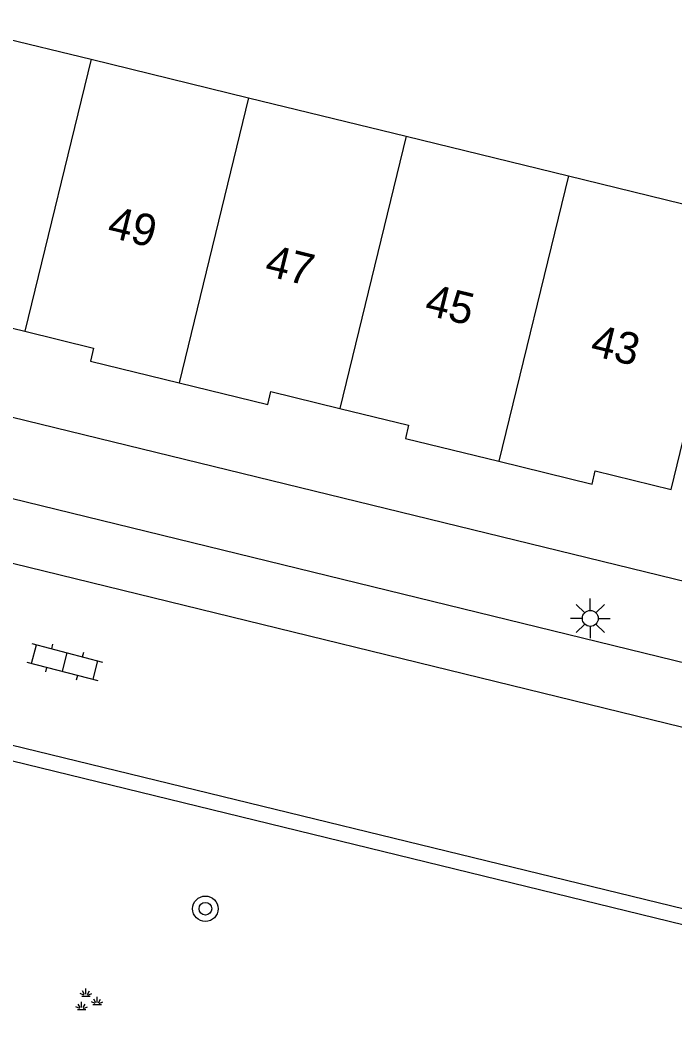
# Model space of a CAD drawing. Extents: x 125000 to 129004, y 397500 to 399008.
# Drawn here: x 126685.74 to 126706.31, y 398431.59 to 398463.62 of the extents above; entities that cross this region are included whole.
import ezdxf

# ---------------------------------------------------------------- set-up
doc = ezdxf.new("R2010")
doc.units = 0
for name, color, linetype in [('gg-anno-huisnummerreeks BGT', 7, 'Continuous'), ('gg-bbg-hoofdgebouw', 7, 'Continuous'), ('gg-bbg-tussenscheiding', 7, 'Continuous'), ('gg-knt-verharding', 7, 'Continuous'), ('gg-knt-verharding nz', 7, 'Continuous'), ('gt-symb-boom', 7, 'Continuous'), ('gt-symb-groenvak', 7, 'Continuous'), ('gt-symb-klinker verharding', 7, 'Continuous'), ('gt-symb-lichtmast', 7, 'Continuous')]:
    doc.layers.add(name, color=color, linetype=linetype)

# ---------------------------------------------------------------- blocks, each defined once
blk = doc.blocks.new('gt0-LMAST')
at = {"layer": 'gt-symb-lichtmast'}
for p, q in [((-0.182, 0.173), (-0.447, 0.438)), ((-0.005, 0.246), (-0.005, 0.621)), ((0.172, 0.173), (0.437, 0.438)), ((-0.255, -0.004), (-0.63, -0.004)), ((-0.182, -0.181), (-0.447, -0.446)), ((-0.005, -0.254), (-0.005, -0.629)), ((0.437, -0.446), (0.172, -0.181)), ((0.245, -0.004), (0.62, -0.004))]:
    blk.add_line(p, q, dxfattribs=at)
blk.add_circle((-0.005, -0.004), 0.25, dxfattribs=at)
blk = doc.blocks.new('gt0-GRVAK')
at = {"layer": 'gt-symb-groenvak'}
for p, q in [((-0.091, 0.211), (-0.156, 0.322)), ((-0.047, 0.214), (-0.047, 0.393)), ((-0.004, 0.211), (0.061, 0.322)), ((-0.11, 0.189), (-0.228, 0.24)), ((-0.182, 0.153), (0.088, 0.153)), ((0.015, 0.189), (0.133, 0.24)), ((0.262, -0.052), (0.197, 0.059)), ((0.305, -0.049), (0.305, 0.13)), ((0.349, -0.052), (0.414, 0.059)), ((-0.245, -0.228), (-0.363, -0.177)), ((-0.318, -0.264), (-0.047, -0.264)), ((-0.226, -0.206), (-0.291, -0.095)), ((-0.183, -0.203), (-0.183, -0.024)), ((-0.139, -0.206), (-0.074, -0.095)), ((-0.12, -0.228), (-0.002, -0.177)), ((0.243, -0.074), (0.125, -0.023)), ((0.17, -0.11), (0.441, -0.11)), ((0.368, -0.074), (0.486, -0.023))]:
    blk.add_line(p, q, dxfattribs=at)
blk = doc.blocks.new('gt0-BOOM')
at = {"layer": 'gt-symb-boom'}
for radius in [0.4, 0.2]:
    blk.add_circle((0, 0), radius, dxfattribs=at)
blk = doc.blocks.new('gt0-KL1')
at = {"layer": 'gt-symb-klinker verharding'}
for p, q in [((-0.5, 0.3), (-0.5, 0.45)), ((0.5, 0.3), (0.5, 0.45)), ((-1.15, 0.3), (1.15, 0.3)), ((-1, -0.3), (-1, 0.3)), ((0, -0.3), (0, 0.3)), ((1, -0.3), (1, 0.3)), ((-1.15, -0.3), (1.15, -0.3)), ((-0.5, -0.45), (-0.5, -0.3)), ((0.5, -0.45), (0.5, -0.3))]:
    blk.add_line(p, q, dxfattribs=at)

msp = doc.modelspace()

# ---------------------------------------------------------------- linework, layer by layer
at = {"layer": 'gg-bbg-hoofdgebouw'}
for p, q in [((126683.009, 398463.61), (126687.961, 398462.401)), ((126687.961, 398462.401), (126692.913, 398461.191)), ((126692.913, 398461.191), (126697.867, 398459.981)), ((126697.867, 398459.981), (126702.968, 398458.736)), ((126702.968, 398458.736), (126709.472, 398457.147))]:
    msp.add_line(p, q, dxfattribs=at)
for points in [[(126680.822, 398454.657), (126683.616, 398453.978), (126683.711, 398454.385), (126685.874, 398453.855)], [(126685.874, 398453.855), (126688.036, 398453.325), (126687.936, 398452.917), (126690.725, 398452.233)], [(126690.725, 398452.233), (126693.514, 398451.548), (126693.614, 398451.959), (126695.779, 398451.43)], [(126695.779, 398451.43), (126697.943, 398450.901), (126697.841, 398450.483), (126700.778, 398449.767)], [(126700.778, 398449.767), (126703.714, 398449.051), (126703.806, 398449.463), (126706.198, 398448.877), (126706.766, 398451.212), (126707.941, 398450.923)]]:
    msp.add_lwpolyline(points, dxfattribs=at)
at = {"layer": 'gg-bbg-tussenscheiding'}
for p, q in [((126687.961, 398462.401), (126685.874, 398453.855)), ((126692.913, 398461.191), (126690.725, 398452.233)), ((126697.867, 398459.981), (126695.779, 398451.43)), ((126702.968, 398458.736), (126700.778, 398449.767))]:
    msp.add_line(p, q, dxfattribs=at)
at = {"layer": 'gg-knt-verharding'}
for p, q in [((126624.185, 398466.129), (126706.733, 398445.964)), ((126655.268, 398447.735), (126721.349, 398431.592)), ((126681.272, 398441.869), (126721.669, 398432.029))]:
    msp.add_line(p, q, dxfattribs=at)
msp.add_lwpolyline([(126711.053, 398440.318), (126711.474, 398442.243), (126683.083, 398449.171)], dxfattribs=at)
at = {"layer": 'gg-knt-verharding nz'}
msp.add_line((126682.599, 398447.27), (126711.053, 398440.318), dxfattribs=at)

# ---------------------------------------------------------------- block references
at = {"layer": 'gt-symb-boom'}
msp.add_blockref('gt0-BOOM', (126691.553, 398435.705), dxfattribs=at)
at = {"layer": 'gt-symb-groenvak'}
msp.add_blockref('gt0-GRVAK', (126687.846, 398432.803), dxfattribs=at)
at = {"layer": 'gt-symb-klinker verharding', "rotation": -14.536509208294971}
msp.add_blockref('gt0-KL1', (126687.131, 398443.457), dxfattribs=at)
at = {"layer": 'gt-symb-lichtmast'}
msp.add_blockref('gt0-LMAST', (126703.66, 398444.834), dxfattribs=at)

# ---------------------------------------------------------------- texts
at = {"layer": 'gg-anno-huisnummerreeks BGT'}
for s, p in [('49', (126688.427, 398456.833)), ('47', (126693.379, 398455.621)), ('45', (126698.407, 398454.389)), ('43', (126703.616, 398453.113))]:
    msp.add_text(s, height=1, rotation=346.2, dxfattribs=at).set_placement(p)

doc.saveas('drawing.dxf')
